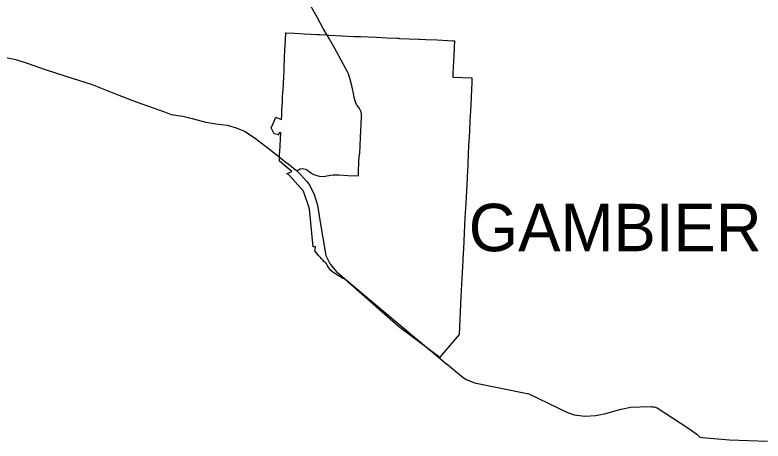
# Model space of a CAD drawing. Extents: x 1851937 to 2123937, y 78841 to 965467.
# Drawn here: x 1989052 to 2006694, y 859166 to 869220 of the extents above; entities that cross this region are included whole.
import ezdxf

# ---------------------------------------------------------------- set-up
doc = ezdxf.new("R2010")
doc.units = 0
for name, color, linetype in [('GM_X_Corporation', 7, 'Continuous'), ('GM_X_Corporation_Text', 7, 'Continuous'), ('GM_X_State_Route', 7, 'Continuous')]:
    doc.layers.add(name, color=color, linetype=linetype)

msp = doc.modelspace()

# ---------------------------------------------------------------- linework, layer by layer
at = {"layer": 'GM_X_Corporation'}
msp.add_lwpolyline([(1995204, 866809), (1995338, 866752), (1995343, 866859), (1995346, 866909), (1995349, 866965), (1995354, 867070), (1995360, 867175), (1995362, 867228), (1995365, 867280), (1995370, 867385), (1995372, 867415), (1995374, 867444), (1995398, 867918), (1995400, 867958), (1995412, 868216), (1995420, 868390), (1995431, 868635), (1995439, 868798), (1995647, 868787), (1995871, 868775), (1996183, 868758), (1996239, 868755), (1996381, 868748), (1996416, 868746), (1996451, 868744), (1996760, 868727), (1996770, 868727), (1997048, 868715), (1997202, 868708), (1997574, 868692), (1997706, 868686), (1997826, 868681), (1998068, 868670), (1998088, 868669), (1998094, 868669), (1998119, 868668), (1998573, 868648), (1998593, 868647), (1998742, 868641), (1999009, 868629), (1999379, 868613), (1999414, 868612), (1999399, 868269), (1999392, 868116), (1999386, 867984), (1999379, 867844), (1999375, 867754), (1999830, 867738), (1999825, 867620), (1999817, 867470), (1999799, 867095), (1999787, 866840), (1999782, 866729), (1999769, 866472), (1999764, 866359), (1999757, 866243), (1999751, 866138), (1999748, 866092), (1999747, 866066), (1999743, 866003), (1999738, 865865), (1999733, 865781), (1999731, 865657), (1999717, 865408), (1999714, 865387), (1999713, 865375), (1999682, 864772), (1999665, 864441), (1999628, 863702), (1999622, 863583), (1999616, 863467), (1999613, 863423), (1999570, 862573), (1999524, 861678), (1999114, 861193), (1999068, 861138), (1998095, 861872), (1996842, 862977), (1996812, 862991), (1996768, 863012), (1996726, 863038), (1996680, 863065), (1996655, 863081), (1996619, 863103), (1996584, 863127), (1996547, 863153), (1996504, 863186), (1996498, 863193), (1996453, 863255), (1996415, 863314), (1996390, 863359), (1996386, 863363), (1996359, 863388), (1996340, 863406), (1996322, 863424), (1996297, 863450), (1996275, 863474), (1996255, 863497), (1996219, 863539), (1996122, 863652), (1996130, 863686), (1996137, 863732), (1996138, 863749), (1996086, 863751), (1996001, 864637), (1995997, 864648), (1995858, 865063), (1995527, 865434), (1995506, 865457), (1995462, 865468), (1995466, 865470), (1995525, 865501), (1995578, 865527), (1995390, 865682), (1995287, 865767), (1995292, 865865), (1995294, 865913), (1995305, 866116), (1995314, 866304), (1995315, 866315), (1995316, 866333), (1995320, 866409), (1995322, 866442), (1995284, 866436), (1995271, 866389), (1995272, 866388), (1995168, 866417), (1995097, 866559), (1995139, 866658)], close=True, dxfattribs=at)
at = {"layer": 'GM_X_State_Route'}
msp.add_line((1997183, 865953), (1997201, 866326), dxfattribs=at)
for points in [[(1996412, 868743), (1996322, 868902), (1996184, 869150), (1995953, 869566), (1995813, 869816), (1995468, 870438)], [(1984717, 868861), (1984764, 868854), (1985644, 868734), (1986255, 868651), (1987203, 868512), (1987971, 868355), (1988543, 868271), (1988762, 868233), (1989076, 868165), (1989386, 868069), (1989738, 867943)], [(1997201, 866326), (1997223, 866812), (1997222, 866879), (1997215, 866933), (1997196, 866980), (1997158, 867036), (1997120, 867086), (1997092, 867141), (1997055, 867275), (1997044, 867325), (1997001, 867519), (1996951, 867726), (1996937, 867777), (1996917, 867829), (1996903, 867860), (1996592, 868425), (1996412, 868743)], [(1989738, 867943), (1990253, 867776), (1990872, 867582), (1991032, 867512), (1991461, 867345), (1991913, 867167), (1992576, 866937), (1992738, 866874), (1993013, 866831), (1993228, 866779), (1993554, 866691), (1993789, 866652), (1994053, 866620), (1994271, 866560), (1994463, 866477), (1994690, 866330), (1995022, 866078), (1995204, 865933), (1995370, 865803)], [(1997151, 865423), (1997157, 865541), (1997164, 865731), (1997171, 865896), (1997183, 865953)], [(1995370, 865803), (1995412, 865771), (1995527, 865683), (1995624, 865604), (1995693, 865546), (1995782, 865460), (1995867, 865368), (1995940, 865284), (1996008, 865198), (1996112, 864982), (1996185, 864733), (1996242, 864380), (1996383, 863541), (1996482, 863337), (1996640, 863153)], [(1995693, 865546), (1995740, 865569), (1995781, 865587), (1995824, 865595), (1995864, 865591), (1995903, 865581), (1995937, 865562), (1996021, 865500), (1996072, 865470), (1996119, 865446), (1996170, 865428), (1996237, 865412), (1996301, 865410), (1996369, 865415), (1996491, 865437), (1996558, 865446), (1996588, 865447)], [(1996588, 865447), (1996628, 865449), (1996689, 865449), (1996902, 865433), (1997151, 865423)], [(1996640, 863153), (1996664, 863133), (1998040, 861981), (1999237, 860979)], [(1999237, 860979), (1999241, 860976), (1999579, 860693), (1999693, 860619), (1999791, 860579)], [(1999791, 860579), (1999891, 860539), (2001171, 860278), (2002083, 859839), (2002239, 859788), (2002493, 859752), (2002747, 859765), (2002988, 859818), (2003200, 859878)], [(2003200, 859878), (2003350, 859920), (2003572, 859965), (2003793, 859975), (2004051, 859978), (2004073, 859973), (2004125, 859974), (2004199, 859949), (2004921, 859476), (2005135, 859328), (2005200, 859257), (2005258, 859247), (2005901, 859193), (2006795, 859166)]]:
    msp.add_lwpolyline(points, dxfattribs=at)

# ---------------------------------------------------------------- texts
at = {"layer": 'GM_X_Corporation_Text'}
msp.add_text('GAMBIER', height=1120, rotation=0, dxfattribs=at).set_placement((1999754, 863644))

doc.saveas('drawing.dxf')
